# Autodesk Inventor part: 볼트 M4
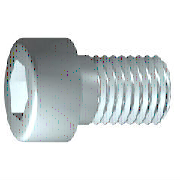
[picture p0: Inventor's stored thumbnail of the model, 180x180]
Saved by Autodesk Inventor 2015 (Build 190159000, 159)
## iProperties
IsCustomPart: 1
Created: 2012-02
Part Number: 볼트 M4
Material: 강철, 연강
Description: 6각머리 태핑 나사
Document SubType Name: Modeling
Standard: KS B 1003
Designer: mduedu
Standards Organization: KS
Language: ko-KR
Size Designation: M 4 x 12
Categories: <MemberInstance><Categories><Category DisplayName="조임쇠" InternalName="e4da775c-781d-43d5-af7c-5136215cf5a6" Mnemonic="FSTN"><Category DisplayName="볼트" InternalN
Density: 1 g/cm^3
Appearance: 강철
Author: mduedu
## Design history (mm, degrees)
sketch "스케치1"
  geometry: L1 (-1, 0)-(12, 0); L2 (12, 0)-(12, 2); L3 (12, 2)-(1.75, 2); L4 (1.75, 2)-(1.32, 2); L5 (1.32, 2)-(0, 2); L6 (0, 2)-(0, 3.5); L7 (0, 3.5)-(-4, 3.5); L8 (-4, 3.5)-(-4, 1.732); L9 (-4, 1.732)-(-2, 1.732); L10 (-2, 1.732)-(-1, 0); L11 (-7.2, 0)-(15.2, 0) reference; L12 (0, -0.7)-(0, 4.2) reference; L13 (1.75, 2)-(0, 2)
  constraints: 22 end point, 6 parallel, 2 collinear, 2 perpendicular, 1 horizontal, 1 point on line
  dimensions: "d1" = 10.25 distance from line of L3.end L2 (= GEL); "d2" = 0.42952 distance of L4.end L3.end (computed from GAL); "d3" = 4 distance between parallel lines of L8 L6 (= KOH); "d4" = 2 distance of L8.end L9.end (= INTI); "d5" = 60 deg angle of L10 L1; "d6" = 4 diameter of L3 L1 (= GD); "d7" = 4 diameter of L5 L1 (= BDM); "d8" = 3.4641 diameter of L9 L1 (= 1.1547 x SW); "d9" = 7 diameter of L7 L1 (= KOD); "d26" = 12 distance between parallel lines of L12 L2 (= NLG)
revolve "본체" sketch "스케치1" stored, may be unused: angle "d10" = 90 deg
sketch "스케치2"
  geometry: L1 (0, -4.9)-(0, 4.9) reference; L2 (-4.9, 0)-(4.9, 0) reference; L3 (1.732, 0)-(0.866, -1.5); L4 (0.866, -1.5)-(-0.866, -1.5); L5 (-0.866, -1.5)-(-1.732, 0); L6 (-1.732, 0)-(-0.866, 1.5); L7 (-0.866, 1.5)-(0.866, 1.5); L8 (0.866, 1.5)-(1.732, 0); 2 further points
  constraints: 12 end point, 1 coincident, 1 horizontal alignment, 1 point on line, 12 other
extrude "슬롯" join sketch "스케치2" stored distance "d11" = 10; taper "d12" = 0 deg
workplane "Work Plane1"
fillet "Fillet2" dims "d30" = 0.1 (= R)
body "Solid1"
fillet "모깎기1" dims "d17" = 0.4 (= RR)
feature "스레드" dims "d13" = 10.25 (= GEL), "d14" = 0
chamfer "모따기1" distance "d15" = 0.42941 (= -0.5 x SPD + 0.5 x GD); stored, may be unused: second distance "d16" = 0.42941 (= GUL), angle "d27" = 45 deg
other parameters: "GD" = 4 (= NND) [user parameter; used in 2 equation terms], "NLG" = 12 [user parameter; used in 1 equation term], "GEL" = 10.25 [user parameter; used in 2 equation terms], "KOD" = 7 [user parameter; used in 1 equation term], "KOH" = 4 [user parameter; used in 1 equation term], "INTI" = 2 [user parameter; used in 1 equation term], "GAL" = 0.42941 (= 0.61345 x PTC) [user parameter; used in 1 equation term], "GUL" = 0.42941 (= 0.61345 x PTC) [user parameter; used in 1 equation term], "BDM" = 4 (= NND) [user parameter; used in 1 equation term], "SW" = 3 [user parameter; used in 2 equation terms], "RR" = 0.4 [user parameter; used in 1 equation term], "SPD" = 3.14117 (= NND - 1.2269 x PTC) [user parameter; used in 1 equation term], "d19" = 0, "d28" = 0, "d29" = 0, "R" = 0.1 [user parameter; used in 1 equation term], "PHH" = 0.2 [user parameter], "GD1" = 3.14117 (= THREADDIA - 1.2269 x PTC) [user parameter], "THREADDIA" = 4 [user parameter; used in 1 equation term], "FAWI" = 45 deg [user parameter], "TPU" = 14.28571 (computed from PTC) [user parameter], "PTC" = 0.7 [user parameter; used in 5 equation terms], "NND" = 4 [user parameter; used in 3 equation terms], "TOA" = 30 deg [user parameter], "E0" = 3.465 (= 1.155 x SW) [user parameter]
